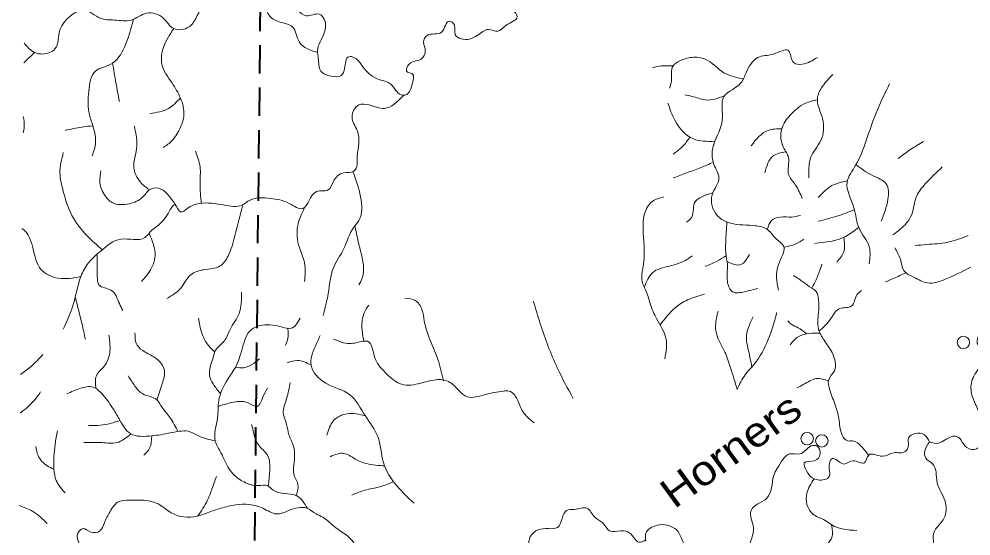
# Model space of a CAD drawing. Extents: x 789498 to 796992, y 8506099 to 8514989.
# Drawn here: x 789526 to 793559, y 8509460 to 8511652 of the extents above; entities that cross this region are included whole.
import ezdxf

# ---------------------------------------------------------------- set-up
doc = ezdxf.new("R2010")
doc.units = 0
doc.header["$LTSCALE"] = 40
doc.linetypes.add('MEDIUM_DASHED', pattern=[4.5, 3, -1.5])
doc.layers.add('15', color=7, linetype='Continuous', lineweight=13)
doc.layers.add('63', color=7, linetype='MEDIUM_DASHED', lineweight=40)

msp = doc.modelspace()

# ---------------------------------------------------------------- linework, layer by layer
at = {"layer": '15'}
msp.add_line((789591.99, 8511510.53), (789546.97, 8511465.81), dxfattribs=at)
for centre in [(793526.77, 8510280.71), (792864.9, 8509872.72), (792927.25, 8509863.12)]:
    msp.add_circle(centre, 26.35, dxfattribs=at)
for points in [[(792948.03, 8512205.24), (792917.26, 8512179.9), (792888.48, 8512147.5), (792874.09, 8512140.3), (792838.12, 8512140.3), (792787.76, 8512118.7), (792748.2, 8512104.3), (792708.63, 8512086.3), (792683.45, 8512057.5), (792654.67, 8512035.9), (792597.12, 8512035.9), (792553.95, 8512050.3), (792532.37, 8512100.7), (792550.35, 8512136.7), (792553.95, 8512158.3), (792485.61, 8512158.3), (792449.64, 8512147.5), (792413.66, 8512115.1), (792374.1, 8512104.3), (792338.13, 8512082.7), (792312.95, 8512046.7), (792258.99, 8512064.7), (792215.82, 8512075.5), (792172.66, 8512061.1), (792169.06, 8512025.1), (792176.26, 8511985.51), (792161.87, 8511920.71), (792111.51, 8511852.31), (792050.36, 8511819.91), (791960.43, 8511812.71), (791892.08, 8511783.91), (791802.16, 8511776.71), (791744.6, 8511733.51), (791719.42, 8511701.11), (791690.65, 8511711.91), (791661.87, 8511744.31), (791633.09, 8511765.91), (791611.51, 8511758.71), (791586.33, 8511733.51), (791579.14, 8511711.91), (791615.11, 8511690.31), (791636.69, 8511661.51), (791589.93, 8511625.51), (791553.96, 8511600.32), (791514.39, 8511607.52), (791467.63, 8511582.32), (791399.28, 8511567.92), (791374.1, 8511585.92), (791370.5, 8511625.51), (791348.92, 8511643.51), (791316.55, 8511596.72), (791254.68, 8511582.32), (791240.29, 8511553.52), (791247.48, 8511517.52), (791229.5, 8511481.52), (791193.52, 8511470.72), (791168.35, 8511441.92), (791168.35, 8511431.12), (791189.93, 8511420.32), (791189.93, 8511369.92), (791164.75, 8511330.32), (791146.76, 8511330.32), (791100, 8511377.12), (791053.24, 8511395.12), (790988.49, 8511441.92), (790945.32, 8511488.72), (790923.74, 8511492.32), (790905.76, 8511441.92), (790891.37, 8511413.12), (790848.2, 8511409.52), (790805.04, 8511431.12), (790794.25, 8511485.12), (790790.65, 8511517.52), (790819.43, 8511593.12), (790819.43, 8511650.71), (790797.84, 8511672.31), (790743.89, 8511665.11), (790707.92, 8511690.31), (790689.93, 8511751.51), (790697.12, 8511819.91), (790653.96, 8511845.11), (790610.79, 8511881.11), (790560.43, 8511870.31), (790513.67, 8511938.71), (790477.7, 8511992.71), (790427.34, 8512025.1), (790380.58, 8512039.5), (790333.82, 8512050.3), (790312.23, 8512100.7), (790312.23, 8512172.7), (790305.04, 8512266.3)], [(794022.17, 8512071.41), (794015.97, 8512028.82), (794054.34, 8512024.02), (794078.32, 8512052.82), (794121.49, 8512024.02), (794179.04, 8511966.42), (794217.41, 8511932.82), (794217.41, 8511899.22), (794207.82, 8511860.82), (794164.65, 8511827.22), (794150.27, 8511764.83), (794131.08, 8511716.83), (794097.51, 8511692.83), (794073.53, 8511649.63), (794073.53, 8511620.83), (794035.16, 8511606.43), (794001.59, 8511558.43), (794001.59, 8511520.03), (793924.85, 8511515.23), (793872.09, 8511510.43), (793819.33, 8511467.24), (793795.35, 8511400.04), (793780.96, 8511347.24), (793771.37, 8511323.24), (793742.59, 8511328.04), (793718.61, 8511352.04), (793685.04, 8511347.24), (793670.65, 8511280.04), (793665.86, 8511236.84), (793694.63, 8511236.84), (793709.02, 8511227.24), (793699.43, 8511179.24), (793689.84, 8511136.04), (793675.45, 8511102.45), (793665.86, 8511064.05), (793685.04, 8511044.85), (793689.84, 8511030.45), (793675.45, 8511006.45), (793670.65, 8510972.85), (793694.63, 8510958.45), (793733, 8510972.85), (793756.98, 8510996.85), (793790.56, 8510977.65), (793819.33, 8510967.09), (793843.31, 8510938.29), (793876.89, 8510919.09), (793915.26, 8510919.09), (793958.42, 8510909.49), (793991.99, 8510890.29), (794011.18, 8510861.49), (793996.79, 8510808.69), (794006.38, 8510727.09), (794001.59, 8510626.3), (794015.97, 8510563.9), (794059.14, 8510530.3), (794063.94, 8510491.9), (794049.55, 8510458.3), (794006.38, 8510453.5), (793963.22, 8510487.1), (793910.46, 8510491.9), (793867.29, 8510487.1), (793814.54, 8510487.1), (793776.17, 8510453.5), (793752.19, 8510419.9), (793752.19, 8510391.1), (793718.61, 8510376.7), (793694.63, 8510371.9), (793685.04, 8510343.1), (793651.47, 8510328.71), (793617.9, 8510323.91), (793589.12, 8510304.71), (793589.12, 8510271.11), (793632.28, 8510266.31), (793699.43, 8510275.91), (793728.21, 8510275.91), (793728.21, 8510247.11), (793675.45, 8510218.31), (793627.49, 8510199.11), (793589.12, 8510165.51), (793560.34, 8510107.91), (793565.14, 8510050.31), (793589.12, 8509992.71), (793608.3, 8509935.12), (793617.9, 8509896.72), (793598.71, 8509877.52), (793589.12, 8509834.32), (793550.75, 8509829.52), (793521.97, 8509858.32), (793497.99, 8509882.32), (793450.03, 8509867.92), (793421.25, 8509853.52), (793382.88, 8509858.32)], [(790791, 8511510.51), (790714.06, 8511553.88), (790685.29, 8511618.68), (790627.73, 8511640.28), (790584.57, 8511669.08), (790570.18, 8511726.67), (790570.18, 8511762.67), (790505.43, 8511798.67), (790469.46, 8511798.67), (790440.68, 8511755.47), (790404.71, 8511769.87), (790375.93, 8511762.67), (790332.77, 8511741.07), (790275.22, 8511654.68), (790246.44, 8511618.68), (790181.69, 8511611.48), (790138.53, 8511654.68), (790066.58, 8511676.28), (790001.84, 8511647.48), (789929.89, 8511647.48), (789872.34, 8511654.68), (789800.4, 8511690.67), (789750.04, 8511669.08), (789699.68, 8511604.28), (789678.1, 8511525.08), (789627.74, 8511503.48), (789591.77, 8511510.68), (789547.88, 8511548.92)], [(790011.08, 8511649.28), (789973.06, 8511532.28), (789915.51, 8511460.28), (789850.76, 8511431.48), (789821.98, 8511345.08), (789821.98, 8511258.69), (789836.37, 8511208.29), (789850.76, 8511129.09), (789836.37, 8511071.49)], [(790181.69, 8511611.48), (790138.53, 8511532.28), (790131.33, 8511460.28), (790174.5, 8511381.08), (790210.47, 8511316.29), (790224.86, 8511244.29), (790210.47, 8511193.89), (790174.5, 8511136.29), (790138.53, 8511107.49)], [(792908.29, 8511489.08), (792843.55, 8511460.28), (792807.57, 8511467.48), (792785.99, 8511517.88), (792721.24, 8511503.48), (792656.5, 8511489.08), (792606.14, 8511424.28), (792584.55, 8511381.08), (792512.61, 8511323.48), (792505.42, 8511222.69), (792469.45, 8511121.89), (792469.45, 8511035.49), (792491.03, 8510977.89), (792462.25, 8510905.9), (792483.84, 8510819.5), (792527, 8510790.7), (792634.91, 8510776.3), (792692.47, 8510761.9), (792735.63, 8510718.7), (792764.41, 8510689.9), (792742.83, 8510610.7), (792742.83, 8510502.71)], [(789922.68, 8511467.05), (789937.09, 8511381.08), (789951.48, 8511301.89)], [(792296.79, 8511453.08), (792246.43, 8511453.08), (792210.46, 8511445.88)], [(792593.24, 8511398.07), (792512.61, 8511424.28), (792433.48, 8511481.88), (792375.92, 8511489.08), (792325.56, 8511474.68), (792296.79, 8511453.08), (792289.59, 8511388.28), (792282.4, 8511359.48)], [(792973.04, 8511417.08), (792929.88, 8511366.68), (792908.29, 8511316.29), (792929.88, 8511229.89), (792922.68, 8511136.29), (792879.52, 8511064.29), (792872.32, 8511006.69), (792872.32, 8510977.89)], [(793214.05, 8511377.49), (793163.69, 8511269.49), (793113.33, 8511132.69), (793070.17, 8511031.9), (793034.2, 8510959.9), (793062.97, 8510851.9), (793084.56, 8510765.5), (793127.72, 8510686.31), (793127.72, 8510614.31)], [(791155.07, 8511327.68), (791073.77, 8511273.09), (791009.02, 8511287.49), (790965.86, 8511287.49), (790937.08, 8511237.09), (790958.66, 8511179.49), (790965.86, 8511121.89), (790958.66, 8511064.29), (790958.66, 8511035.49), (790944.28, 8511006.69), (790901.11, 8510999.49), (790857.95, 8510963.49), (790836.36, 8510927.5), (790786, 8510920.3), (790728.45, 8510848.3), (790670.9, 8510869.9), (790591.76, 8510891.5), (790505.43, 8510884.3), (790469.46, 8510862.7), (790397.52, 8510862.7), (790289.6, 8510869.9), (790239.24, 8510848.3), (790210.47, 8510833.9), (790188.89, 8510862.7), (790152.91, 8510819.5), (790080.97, 8510747.5), (790059.39, 8510725.9), (789958.67, 8510718.7), (789872.34, 8510668.3), (789814.79, 8510610.7), (789786.01, 8510553.11), (789757.23, 8510445.11), (789714.07, 8510337.11)], [(790209.99, 8511317.19), (790160.11, 8511273.09), (790080.97, 8511251.49)], [(792472.23, 8511133.5), (792383.12, 8511143.49), (792303.98, 8511222.69), (792275.2, 8511294.69)], [(792513.92, 8511326.3), (792433.48, 8511309.09), (792404.7, 8511316.29), (792347.15, 8511330.68)], [(792907.99, 8511309.27), (792857.93, 8511294.69), (792793.19, 8511244.29), (792757.22, 8511186.69), (792764.41, 8511107.49), (792785.99, 8511064.29), (792785.99, 8510992.29), (792814.77, 8510949.1), (792843.55, 8510891.5)], [(789544.49, 8511238.32), (789548.6, 8511193.89), (789543.74, 8511168.98)], [(789838.71, 8511199.65), (789793.2, 8511193.89), (789721.26, 8511179.49)], [(790079.11, 8510927.04), (790041.4, 8510959.88), (790012.63, 8511022.27), (790024.62, 8511101.47), (790015.03, 8511197.47)], [(792757.22, 8511186.69), (792699.66, 8511179.49), (792627.72, 8511114.69)], [(792366.45, 8511147.91), (792332.76, 8511107.49), (792296.79, 8511078.69)], [(793357.94, 8511132.69), (793300.38, 8511096.7), (793250.02, 8511060.7)], [(790298.5, 8510871.21), (790293.2, 8510952.68), (790293.2, 8511024.68), (790274.02, 8511091.87)], [(789879.18, 8510673.6), (789814.79, 8510733.1), (789750.04, 8510819.5), (789714.07, 8510920.3), (789699.68, 8510999.49), (789714.07, 8511085.89)], [(792773.71, 8511088.6), (792721.24, 8511071.49), (792685.27, 8510999.49)], [(792468.41, 8511044.83), (792411.89, 8511021.09), (792354.34, 8510999.49), (792296.79, 8510977.89)], [(793071.31, 8511034.53), (793142.11, 8510988.7), (793199.66, 8510952.7), (793206.86, 8510887.9), (793178.08, 8510794.3)], [(793437.07, 8511024.7), (793365.13, 8510952.7), (793329.16, 8510902.3), (793307.58, 8510823.1), (793285.99, 8510787.1), (793228.44, 8510736.71)], [(790190.62, 8510863.78), (790161.31, 8510902.28), (790127.73, 8510931.08), (790084.57, 8510931.08), (790051, 8510897.48), (789993.44, 8510868.68), (789921.5, 8510873.48), (789887.93, 8510907.08), (789868.74, 8510964.68), (789873.54, 8511007.87)], [(790940.78, 8511004.13), (790973.05, 8510898.7), (790965.86, 8510797.9), (790944.28, 8510769.1), (790901.11, 8510675.5), (790857.95, 8510596.3), (790836.36, 8510488.31), (790814.78, 8510394.71)], [(793034.06, 8510965.35), (792969.45, 8510945.5), (792911.9, 8510895.1)], [(792262.02, 8510211.12), (792266.82, 8510297.51), (792228.45, 8510379.11), (792199.67, 8510446.31), (792180.49, 8510503.91), (792166.1, 8510537.51), (792170.9, 8510604.7), (792170.9, 8510743.9), (792175.69, 8510825.5), (792209.27, 8510878.3), (792257.23, 8510897.5)], [(792463.79, 8510914.78), (792419.09, 8510898.7), (792390.31, 8510877.1), (792375.92, 8510812.3), (792354.34, 8510790.7)], [(790475.07, 8510863.99), (790440.68, 8510733.1), (790411.91, 8510646.7), (790375.93, 8510603.5), (790311.19, 8510589.1), (790253.63, 8510567.51), (790210.47, 8510509.91), (790152.91, 8510466.71)], [(790733.93, 8510847.94), (790706.87, 8510776.3), (790714.06, 8510682.7), (790735.64, 8510617.9), (790735.64, 8510538.71)], [(792696.06, 8510758.31), (792714.05, 8510797.9), (792750.02, 8510812.3), (792800.38, 8510812.3), (792836.35, 8510819.5)], [(793065.1, 8510843.46), (792991.03, 8510815.9), (792911.9, 8510794.3)], [(790948.25, 8510775.39), (790973.05, 8510668.3), (790980.25, 8510553.11), (790965.86, 8510524.31)], [(792525.26, 8510791.11), (792519.81, 8510704.3), (792519.81, 8510661.1), (792527, 8510610.7), (792527, 8510538.71), (792548.58, 8510495.51), (792598.94, 8510495.51), (792656.5, 8510509.91)], [(793083.67, 8510768.97), (793027, 8510729.51), (792897.51, 8510700.71)], [(789788.22, 8510559.5), (789692.49, 8510553.11), (789620.54, 8510589.1), (789584.57, 8510682.7), (789541.41, 8510761.9), (789539.31, 8510763.3)], [(790077.33, 8510743.86), (790102.55, 8510646.7), (790088.17, 8510596.3), (790045, 8510538.71)], [(793547.39, 8510734.3), (793461.06, 8510705.5), (793369.93, 8510695.9), (793321.97, 8510691.1)], [(792767.89, 8510685.13), (792814.77, 8510697.1), (792850.74, 8510718.7)], [(793019.8, 8510726.54), (793019.81, 8510664.71), (792991.03, 8510621.51)], [(789857.29, 8510655.96), (789857.95, 8510560.31), (789865.15, 8510524.31), (789915.51, 8510502.71), (789951.48, 8510445.11), (789965.86, 8510416.31)], [(792175.16, 8510515.47), (792209.27, 8510575.91), (792281.21, 8510604.7), (792357.95, 8510633.5), (792377.13, 8510647.9)], [(792521.07, 8510647.85), (792483.84, 8510625.1), (792433.48, 8510603.5)], [(792525.16, 8510623.59), (792584.55, 8510610.7), (792620.53, 8510653.9)], [(793556.98, 8510599.9), (793446.67, 8510547.11), (793374.73, 8510532.71), (793317.17, 8510556.71), (793274.01, 8510585.51), (793259.62, 8510633.5), (793235.64, 8510681.5)], [(792885.01, 8510510.43), (792908.06, 8510559.09), (792927.25, 8510611.89)], [(793282.98, 8510576.15), (793230.84, 8510551.91), (793197.27, 8510537.51)], [(793124.92, 8509802.74), (793095.11, 8509839.11), (793056.74, 8509863.11), (793037.56, 8509863.11), (793013.58, 8509887.11), (792999.19, 8509959.11), (792984.8, 8510011.9), (792960.82, 8510079.1), (792956.02, 8510122.3), (792980.01, 8510160.7), (792970.41, 8510237.5), (792936.84, 8510290.3), (792912.86, 8510338.3), (792912.86, 8510405.49), (792912.86, 8510463.09), (792903.27, 8510496.69), (792884.08, 8510511.09), (792850.51, 8510535.09), (792807.34, 8510563.89)], [(790379.71, 8510063.12), (790348.36, 8510105.5), (790333.97, 8510139.1), (790348.36, 8510215.9), (790357.95, 8510244.7), (790396.32, 8510287.89), (790420.3, 8510335.89), (790458.67, 8510403.09), (790468.26, 8510494.29)], [(792914.57, 8510327.72), (792965.62, 8510381.49), (793003.99, 8510424.69), (793051.95, 8510434.29), (793075.93, 8510482.29), (793095.11, 8510501.49)], [(789765.57, 8510470.35), (789793.2, 8510358.71), (789807.59, 8510293.91)], [(791324.54, 8510117.39), (791300.4, 8510208.71), (791262.03, 8510304.71), (791242.84, 8510371.9), (791233.25, 8510419.9), (791204.47, 8510458.3), (791161.31, 8510467.9)], [(791873.54, 8510043.12), (791806.39, 8510172.72), (791768.02, 8510263.91), (791734.45, 8510359.91), (791705.67, 8510455.91)], [(792242.44, 8510354.86), (792305.19, 8510427.11), (792357.95, 8510460.71), (792429.89, 8510484.71)], [(790987.01, 8510285.96), (790979.06, 8510343.1), (790988.65, 8510405.5), (791007.83, 8510439.1)], [(792568.98, 8510081.52), (792540.2, 8510172.72), (792516.22, 8510239.91), (792477.85, 8510331.11), (792487.44, 8510412.71)], [(792568.98, 8510081.52), (792602.55, 8510143.92), (792631.33, 8510177.52), (792693.68, 8510278.31), (792736.84, 8510407.91)], [(790355.42, 8510238.99), (790324.37, 8510273.5), (790300.39, 8510321.49), (790286.01, 8510383.89)], [(790747.76, 8509577.09), (790703.27, 8509630.31), (790650.51, 8509639.91), (790602.55, 8509654.31), (790578.57, 8509673.51), (790540.2, 8509673.51), (790492.24, 8509683.11), (790444.28, 8509711.91), (790415.5, 8509745.51), (790381.93, 8509812.71), (790357.95, 8509860.71), (790367.54, 8509961.5), (790372.34, 8510033.5), (790410.71, 8510124.7), (790444.28, 8510177.5), (790473.06, 8510259.1), (790511.42, 8510335.89), (790588.16, 8510355.09), (790640.92, 8510345.49), (790679.29, 8510340.69), (790717.66, 8510383.89)], [(792630.03, 8510175.8), (792616.94, 8510244.71), (792607.35, 8510297.51), (792636.12, 8510388.71)], [(792860.19, 8510318.3), (792826.53, 8510343.1), (792797.75, 8510357.49), (792783.36, 8510371.89)], [(790665.3, 8510337.71), (790664.9, 8510297.49), (790655.31, 8510268.7)], [(789851.94, 8510085.57), (789854.35, 8510139.1), (789892.72, 8510187.1), (789911.91, 8510254.3), (789907.11, 8510311.89)], [(790110.35, 8510036), (790132.53, 8510105.5), (790142.12, 8510163.1), (790108.55, 8510211.1), (790060.59, 8510239.9), (790027.01, 8510268.7), (790017.42, 8510321.49)], [(791199.68, 8509599.13), (791127.74, 8509671.12), (791070.18, 8509771.92), (791046.2, 8509882.32), (790993.44, 8509968.72), (790926.3, 8510059.91), (790825.58, 8510107.91), (790763.23, 8510184.71), (790787.21, 8510275.91), (790801.6, 8510309.51)], [(791708.07, 8509939.92), (791660.11, 8509987.91), (791636.13, 8510040.71), (791602.55, 8510074.31), (791578.57, 8510074.31), (791501.83, 8510059.91), (791425.1, 8510050.31), (791362.75, 8510103.11), (791338.77, 8510117.51), (791228.45, 8510107.91), (791146.92, 8510103.11), (791084.57, 8510146.31), (791036.61, 8510208.71), (791022.22, 8510256.71), (791003.04, 8510285.51), (790983.85, 8510285.51), (790926.3, 8510275.91), (790859.15, 8510295.11)], [(792918.06, 8510319.48), (792874.49, 8510319.1), (792826.53, 8510304.7), (792792.96, 8510271.1)], [(789532.56, 8510144.46), (789577.38, 8510178.72), (789627.74, 8510229.11)], [(790443.37, 8510175.59), (790477.85, 8510172.7), (790521.02, 8510191.9), (790545, 8510211.1)], [(790763.21, 8510185.13), (790705.68, 8510203.91), (790662.51, 8510194.31)], [(790199.81, 8509903.13), (790166.1, 8509961.5), (790132.53, 8510004.7), (790108.55, 8510038.3), (790051, 8510062.3), (790017.42, 8510095.9), (789988.65, 8510139.1)], [(792955.82, 8510117.29), (792903.27, 8510127.1), (792850.51, 8510103.1), (792821.73, 8510088.7)], [(790356.69, 8509863.45), (790286.01, 8509884.71), (790242.84, 8509903.91), (790204.47, 8509903.91), (790127.73, 8509889.51), (790089.36, 8509884.71), (789998.24, 8509894.31), (789950.28, 8509956.7), (789921.5, 8510004.7), (789878.33, 8510062.3), (789839.97, 8510091.1), (789787.21, 8510086.3), (789729.65, 8510062.3)], [(790370.26, 8510009.63), (790444.28, 8510028.7), (790497.04, 8510023.9), (790535.4, 8510009.5), (790559.39, 8510047.9), (790578.57, 8510086.3)], [(790701.06, 8509632.56), (790708.07, 8509678.31), (790693.68, 8509711.91), (790693.68, 8509793.51), (790688.88, 8509841.51), (790669.7, 8509889.51), (790660.1, 8509932.7), (790645.72, 8509980.7), (790660.1, 8510043.1), (790674.49, 8510110.3)], [(789530.77, 8509980.46), (789535.41, 8509984.07), (789592.97, 8510036.86), (789616.95, 8510070.46)], [(790992.73, 8509969.8), (790916.71, 8509978.32), (790859.15, 8509949.52), (790830.38, 8509887.12)], [(789954.54, 8509949.57), (789892.72, 8509932.7), (789849.56, 8509927.91), (789820.78, 8509927.91)], [(790582.15, 8509672.12), (790588.16, 8509735.91), (790578.57, 8509803.11), (790540.2, 8509846.31), (790521.02, 8509894.31), (790511.42, 8509932.7)], [(789722.47, 8509642.32), (789684.1, 8509695.12), (789674.51, 8509743.12), (789679.3, 8509848.72), (789688.9, 8509906.32)], [(790001, 8509892.59), (789940.68, 8509855.91), (789878.33, 8509855.91), (789801.6, 8509855.91)], [(790088.33, 8509884.6), (790079.77, 8509831.91), (790055.79, 8509803.11)], [(793382.88, 8509858.32), (793361.3, 8509889.51), (793322.93, 8509894.31), (793294.15, 8509875.11), (793294.15, 8509846.31), (793279.76, 8509817.51), (793231.8, 8509812.71), (793183.84, 8509798.31), (793126.29, 8509803.11), (793107.1, 8509769.51), (793059.14, 8509779.11), (793020.77, 8509764.71), (792987.2, 8509783.91), (792972.81, 8509788.71), (792958.42, 8509745.51), (792958.42, 8509711.91), (792910.46, 8509697.51), (792886.48, 8509707.11), (792862.5, 8509735.91), (792852.91, 8509769.51), (792896.07, 8509779.11), (792920.05, 8509807.91), (792905.66, 8509841.51), (792881.68, 8509841.51), (792857.7, 8509822.31), (792833.72, 8509807.91), (792790.56, 8509807.91), (792761.78, 8509783.91), (792737.8, 8509745.51), (792723.41, 8509716.71), (792713.82, 8509663.91), (792694.63, 8509620.72), (792656.27, 8509596.72), (792627.49, 8509567.92), (792637.08, 8509495.92), (792627.49, 8509443.12), (792603.51, 8509404.72), (792555.55, 8509419.12), (792488.4, 8509399.92), (792454.83, 8509371.12), (792435.64, 8509371.12), (792411.66, 8509385.52), (792387.68, 8509399.92), (792363.7, 8509404.72), (792339.72, 8509433.52), (792315.74, 8509481.52), (792272.57, 8509505.52), (792229.41, 8509505.52), (792181.45, 8509471.92), (792181.45, 8509438.32)], [(793382.88, 8509858.32), (793362.73, 8509818.94), (793367.53, 8509790.14), (793396.31, 8509766.15), (793410.69, 8509732.55), (793415.49, 8509684.55), (793449.06, 8509607.75), (793449.06, 8509545.35), (793420.29, 8509502.15), (793401.1, 8509473.35), (793401.1, 8509420.55), (793386.71, 8509377.36), (793362.73, 8509343.76), (793362.73, 8509310.16), (793314.77, 8509310.16), (793257.22, 8509286.16), (793214.05, 8509247.76), (793209.26, 8509194.96), (793194.87, 8509137.36), (793175.68, 8509103.76), (793180.48, 8509060.57), (793218.85, 8509031.77), (793233.24, 8509012.57), (793218.85, 8508964.57), (793180.48, 8508902.17), (793146.91, 8508820.57), (793127.72, 8508729.37), (793137.31, 8508700.58), (793170.89, 8508690.98), (793204.46, 8508662.18), (793223.65, 8508585.38), (793228.44, 8508508.58), (793238.03, 8508455.78), (793238.03, 8508398.18), (793209.26, 8508364.58), (793214.05, 8508326.19), (793257.22, 8508330.99), (793295.59, 8508345.39), (793329.16, 8508330.99), (793362.73, 8508297.39), (793410.69, 8508278.19), (793434.68, 8508254.19), (793444.27, 8508196.59), (793449.06, 8508153.39), (793444.27, 8508110.19), (793425.08, 8508062.19), (793425.08, 8508004.59), (793410.69, 8507947), (793372.33, 8507927.8), (793353.14, 8507927.8), (793333.96, 8507894.2), (793329.16, 8507855.8), (793319.57, 8507822.2), (793333.96, 8507774.2), (793305.18, 8507759.8), (793257.22, 8507764.6), (793199.66, 8507783.8), (793156.5, 8507793.4), (793127.72, 8507807.8)], [(789674.51, 8509743.07), (789645.73, 8509757.52), (789607.36, 8509800.72), (789597.77, 8509839.12)], [(791076.23, 8509757.26), (790998.24, 8509767.12), (790950.28, 8509786.32), (790902.32, 8509810.32), (790844.76, 8509795.92)], [(790284.09, 8509544.88), (790324.37, 8509611.11), (790343.56, 8509659.11), (790362.74, 8509711.91)], [(791112.22, 8509689.26), (791046.2, 8509666.32), (790983.85, 8509651.92), (790935.89, 8509632.72)], [(792894.25, 8509702.35), (792863.93, 8509641.35), (792863.93, 8509593.35), (792892.71, 8509550.15), (792940.67, 8509526.15), (792969.45, 8509506.95), (793074.96, 8509482.95)], [(792181.45, 8509443.12), (792152.67, 8509433.52), (792114.3, 8509471.92), (792075.93, 8509481.52), (792027.97, 8509481.52), (791999.19, 8509515.12), (791965.62, 8509539.12), (791932.05, 8509577.52), (791879.29, 8509572.72), (791845.72, 8509567.92), (791826.53, 8509534.32), (791807.35, 8509495.92), (791768.98, 8509491.12), (791725.82, 8509486.32), (791692.24, 8509457.52), (791687.45, 8509414.32), (791721.02, 8509351.92), (791730.61, 8509294.32), (791721.02, 8509275.13), (791663.47, 8509270.33), (791581.93, 8509294.32), (791514.79, 8509289.52), (791452.44, 8509260.73), (791423.66, 8509217.53), (791438.05, 8509179.13), (791466.82, 8509159.93), (791457.23, 8509126.33), (791394.88, 8509107.13), (791342.12, 8509073.53), (791313.35, 8509020.73), (791303.76, 8508982.33), (791265.39, 8508967.93), (791212.63, 8508967.93), (791183.85, 8508996.73), (791183.85, 8509049.53), (791193.44, 8509092.73), (791164.67, 8509164.73), (791121.5, 8509227.13), (791078.34, 8509275.13), (791059.15, 8509294.32), (791049.56, 8509327.92), (791020.78, 8509347.12), (790992.01, 8509356.72), (790943.08, 8509433.52), (790866.34, 8509495.92), (790813.58, 8509539.12), (790784.81, 8509553.52), (790746.44, 8509577.52), (790669.7, 8509567.92), (790616.94, 8509553.52), (790559.39, 8509577.52), (790444.28, 8509591.92), (790381.93, 8509577.52), (790324.38, 8509558.32), (790281.21, 8509543.92), (790170.9, 8509558.32), (790122.94, 8509591.92), (790055.79, 8509611.12), (789993.44, 8509611.12), (789950.28, 8509606.32), (789911.91, 8509563.12), (789887.93, 8509515.12), (789868.75, 8509481.52), (789830.38, 8509476.72), (789796.8, 8509491.12), (789772.82, 8509462.32), (789782.41, 8509423.92), (789796.8, 8509385.52), (789825.58, 8509390.32), (789835.17, 8509366.32), (789839.97, 8509270.33), (789796.8, 8509183.93), (789744.05, 8509126.33), (789720.07, 8509063.93), (789748.84, 8509044.73), (789763.23, 8509001.53), (789806.4, 8508977.53), (789839.97, 8508943.93), (789883.13, 8508915.14), (789897.52, 8508881.54), (789931.1, 8508867.14), (789974.26, 8508804.74), (790007.83, 8508723.14), (789988.65, 8508627.14), (789945.48, 8508526.35), (789907.11, 8508487.95), (789873.54, 8508454.35), (789825.58, 8508372.75), (789796.8, 8508305.55), (789734.45, 8508247.95), (789700.88, 8508199.96)], [(789645.73, 8509512.73), (789583.38, 8509565.53), (789526.5, 8509588.71)], [(792967.76, 8509507.4), (792969.45, 8509454.15), (792950.27, 8509425.35)]]:
    msp.add_spline(points, degree=3, dxfattribs=at)
at = {"layer": '63'}
msp.add_lwpolyline([(795985.61, 8513296.58), (795924.11, 8507761.4), (790507.28, 8507821.14), (790567.65, 8513356.12), (795985.61, 8513296.58)], close=True, dxfattribs=at)

# ---------------------------------------------------------------- texts
at = {"layer": '15', "width": 1.15}
msp.add_text('Horners', height=125, rotation=36.11, dxfattribs=at).set_placement((792301.76, 8509572.23))

doc.saveas('drawing.dxf')
